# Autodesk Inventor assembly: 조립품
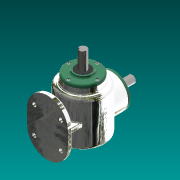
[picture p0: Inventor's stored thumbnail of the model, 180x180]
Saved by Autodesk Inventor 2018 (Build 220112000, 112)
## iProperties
Created: 2023-01
Part Number: 조립품
Material: 일반
Document SubType Name: Assembly
Designer: 강의실01
Author: 강의실01
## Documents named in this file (14)
- C:\Users\kimgi\Desktop\730106V1011\조립품.iam
- C:\Users\kimgi\Desktop\730106V1011\본체.ipt
- C:\Users\kimgi\Desktop\730106V1011\커버.ipt
- C:\Users\kimgi\Desktop\730106V1011\베어링 6203.ipt
- C:\Users\kimgi\Desktop\730106V1011\메인 축.ipt
- 메인 축.ipt
- C:\Users\kimgi\Desktop\730106V1011\서브 축.ipt
- 서브 축.ipt
- C:\Users\kimgi\Desktop\730106V1011\키 5x5.ipt
- C:\Users\kimgi\Desktop\730106V1011\키 4x4.ipt
- C:\Users\kimgi\Desktop\730106V1011\오일실 17 32 8.ipt
- C:\Users\kimgi\Desktop\730106V1011\메인 베벨기어.ipt
- C:\Users\kimgi\Desktop\730106V1011\서브 베벨기어.ipt
- C:\Users\kimgi\Desktop\730106V1011\M4.ipt
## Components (8 placed, 1 different names)
1. M4:1
2. M4:2
3. M4:3
4. M4:4
5. M4:5
6. M4:6
7. M4:7
8. M4:8
